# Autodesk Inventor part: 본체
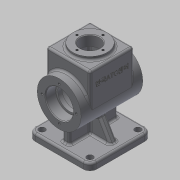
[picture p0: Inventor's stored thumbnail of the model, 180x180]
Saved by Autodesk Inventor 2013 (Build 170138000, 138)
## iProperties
Created: 2019-01
Part Number: 본체
Material: 일반
Document SubType Name: Modeling
Designer: mduedu
Density: 1 g/cm^3
Author: mduedu
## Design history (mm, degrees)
sketch "스케치1"
  geometry: C1 r 32 at (0, 0); 1 further point
  constraints: 1 centre point, 1 coincident
  dimensions: "d0" = 64 diameter of C1
extrude "돌출1" new body sketch "스케치1" stored distance "d1" = 90; taper "d2" = 0 deg
sketch "스케치2"
  geometry: L1 (0, 32)-(50, 32); L2 (50, 32)-(50, -32); L3 (50, -32)-(0, -32); L4 (0, -32)-(0, 32); C1 r 32 at (0, 0) reference; 2 further points
  constraints: 8 end point, 2 parallel, 1 coincident, 1 horizontal, 1 midpoint, 1 perpendicular, 1 tangent
  dimensions: "d5" = 50 distance between parallel lines of L4 L2
extrude "돌출2" join sketch "스케치2" stored distance "d7" = 64; taper "d8" = 0 deg
sketch "스케치3"
  geometry: C1 r 25 at (32, 32); 1 further point
  constraints: 1 centre point, 1 coincident
  dimensions: "d9" = 50 diameter of C1
extrude "돌출3" join sketch "스케치3" distance "d10" = 5; taper "d11" = 0 deg
sketch "스케치4"
  geometry: L1 (40, 25)-(0, 25); L2 (0, 25)-(0, -25); L3 (0, -25)-(40, -25); L4 (40, -25)-(40, 25); L5 (55, -25)-(55, 25) reference; A1 r 25 centre (0, 0) between (0, 25) and (0, -25); A2 r 25 centre (0, 0) between (0, -25) and (0, 25); 2 further points
  constraints: 8 end point, 4 point on circle, 2 centre point, 2 coincident, 2 parallel, 1 horizontal, 1 midpoint, 1 perpendicular, 1 tangent
  dimensions: "d12" = 50 diameter of A1; "d13" = 15 distance between parallel lines of L4 L5
extrude "돌출4" cut sketch "스케치4" stored distance "d14" = 48; taper "d15" = 0 deg
sketch "스케치5"
  geometry: C1 r 20 at (0, 0); 1 further point
  constraints: 1 centre point, 1 coincident
  dimensions: "d16" = 40 diameter of C1
extrude "돌출5" cut sketch "스케치5" distance "d17" = 15; taper "d18" = 0 deg
sketch "스케치6"
  geometry: C1 r 17 at (0, 0); 1 further point
  constraints: 1 centre point, 1 coincident
  dimensions: "d19" = 34 diameter of C1
extrude "돌출6" cut sketch "스케치6" stored distance "d20" = 15; taper "d21" = 0 deg
fillet "모깎기1" dims "d22" = 0.3
fillet "모깎기2" dims "d23" = 3
fillet "모깎기3" dims "d24" = 3
fillet "모깎기4" dims "d25" = 3
fillet "모깎기5" dims "d26" = 3
fillet "모깎기6" dims "d27" = 3
sketch "스케치7"
  geometry: C1 r 14 at (0, 0); 1 further point
  constraints: 1 centre point, 1 coincident
  dimensions: "d28" = 28 diameter of C1
extrude "돌출7" cut sketch "스케치7" stored distance "d29" = 15; taper "d30" = 0 deg
chamfer "모따기1" distance "d31" = 1; stored, may be unused: second distance "d32" = 2, angle "d33" = 45 deg
chamfer "모따기2" distance "d34" = 1; stored, may be unused: second distance "d35" = 2, angle "d36" = 45 deg
node "작업 평면1"
sketch "스케치8"
  geometry: L1 (45, -45)-(-45, -45); L2 (-45, -45)-(-45, 45); L3 (-45, 45)-(45, 45); L4 (45, 45)-(45, -45); 3 further points
  constraints: 8 end point, 2 midpoint, 2 parallel, 1 horizontal, 1 horizontal alignment, 1 perpendicular, 1 vertical alignment
  dimensions: "d39" = 90 distance of L1.start L1.end; "d40" = 90 distance of L1.end L2.end
extrude "돌출8" join sketch "스케치8" distance "d41" = 10; taper "d42" = 0 deg
sketch "스케치9"
  geometry: L1 (-35, 5)-(35, 5); L2 (35, 5)-(35, -5); L3 (35, -5)-(-35, -5); L4 (-35, -5)-(-35, 5); 3 further points
  constraints: 8 end point, 2 midpoint, 2 parallel, 1 horizontal, 1 horizontal alignment, 1 perpendicular, 1 vertical alignment
  dimensions: "d52" = 10 distance of L1.end L2.end; "d54" = 70 distance of L1.start L1.end
extrude "돌출9" join sketch "스케치9" stored distance "d50" = 10; taper "d51" = 0 deg
sketch "스케치10"
  geometry: L1 (0, -25)-(37, -25) reference; L2 (40, -22)-(40, -14) reference; L3 (40, -14)-(54, -14) reference; L4 (54, -14)-(55, -15) reference; L5 (55, -15)-(55, -25) reference; L6 (55, -25)-(53, -25) reference; L7 (50, -28)-(50, -29) reference; L8 (47, -32)-(0, -32) reference; L9 (-31.607, -5)-(-55, -5) reference; L10 (-55, -5)-(-55, -45) reference; L11 (-55, -45)-(-65, -45) reference; L12 (-65, -45)-(-65, 45) reference; L13 (-65, 45)-(-55, 45) reference; L14 (-55, 45)-(-55, 5) reference; L15 (-55, 5)-(-31.607, 5) reference; L16 (0, 32)-(47, 32) reference; L17 (50, 29)-(50, 28) reference; L18 (53, 25)-(55, 25) reference; L19 (55, 25)-(55, 15) reference; L20 (55, 15)-(54, 14) reference; L21 (54, 14)-(40, 14) reference; L22 (40, 14)-(40, 22) reference; L23 (37, 25)-(0, 25) reference; L24 (-55, 35)-(-26.2, 18.372); A1 r 25 centre (0, 0) between (0, 25) and (0, -25) reference; A2 r 3 centre (37, -22) between (37, -25) and (40, -22) reference; A3 r 3 centre (53, -28) between (53, -25) and (50, -28) reference; A4 r 3 centre (47, -29) between (47, -32) and (50, -29) reference; A5 r 32 centre (0, 0) between (-31.607, -5) and (0, -32) reference; A6 r 32 centre (0, 0) between (0, 32) and (-31.607, 5) reference; A7 r 3 centre (47, 29) between (50, 29) and (47, 32) reference; A8 r 3 centre (53, 28) between (50, 28) and (53, 25) reference; A9 r 3 centre (37, 22) between (40, 22) and (37, 25) reference; 1 further point
  constraints: 2 end point, 1 point on circle, 1 point on line
  dimensions: "d55" = 35 vertical distance of L24.start point (0, 0); "d56" = 120 deg angle of L24 L14
feature "리브1" sketch "스케치10" dims "d57" = 1, "d58" = 10, "d59" = 0, "d60" = 0, "d61" = 1, "d62" = 1
fillet "모깎기7" dims "d63" = 3
fillet "모깎기8" dims "d64" = 3
fillet "모깎기9" dims "d65" = 10
sketch "스케치11"
  geometry: L1 (-45, 35)-(-45, -35) reference; L2 (-35, -45)-(35, -45) reference; L3 (45, -35)-(45, 35) reference; L4 (35, 45)-(-35, 45) reference; L5 (8, -29.804)-(8, -8) reference; L6 (-2, -36.732)-(2, -36.732) reference; L7 (-8, -8)-(-8, -29.804) reference; L8 (-32, -8)-(-8, -8) reference; L9 (-38, 2)-(-38, -2) reference; L10 (-8, 8)-(-32, 8) reference; L11 (-8, 29.804)-(-8, 8) reference; L12 (2, 36.732)-(-2, 36.732) reference; L13 (8, 8)-(8, 29.804) reference; L14 (32, 8)-(8, 8) reference; L15 (38, -2)-(38, 2) reference; L16 (8, -8)-(32, -8) reference; A1 r 10 centre (-35, 35) between (-35, 45) and (-45, 35) reference; A2 r 10 centre (-35, -35) between (-45, -35) and (-35, -45) reference; A3 r 10 centre (35, -35) between (35, -45) and (45, -35) reference; A4 r 10 centre (35, 35) between (45, 35) and (35, 45) reference; A5 r 6 centre (-32, -2) between (-38, -2) and (-32, -8) reference; A6 r 6 centre (-32, 2) between (-32, 8) and (-38, 2) reference; A7 r 6 centre (32, 2) between (38, 2) and (32, 8) reference; A8 r 6 centre (32, -2) between (32, -8) and (38, -2) reference; 9 further points; 4 other entities
  constraints: 4 coincident, 4 other
hole "구멍1" sketch "스케치11" at (-35, 35), (35, 35), (35, -35), (-35, -35) diameter "d66" = 9; stored, may be unused: countersink angle "d70" = 90 deg, drill point angle "d72" = 118 deg; dims "d67" = 6, "d68" = 4, "d69" = 2, "d71" = 8
fillet "모깎기10" dims "d73" = 3
sketch "스케치12"
  geometry: L1 (-3, 47)-(-3, 19.596) reference; 2 further points
  constraints: 1 other
  dimensions: "d74" = 32 distance from line of point (29, 30) L1; "d75" = 30 distance of point (29, 30) point (29, 0)
feature "엠보싱1" sketch "스케치12" dims "d76" = 0.5, "d77" = 0
sketch "스케치13"
  geometry: 4 further points
  constraints: 4 other
hole "구멍2" sketch "스케치13" at (-25, 0), (0, -25), (25, 0), (0, 25) diameter "d78" = 3.242; stored, may be unused: countersink angle "d82" = 90 deg, drill point angle "d84" = 120 deg; dims "d79" = 7, "d80" = 4, "d81" = 2, "d83" = 9
sketch "스케치14"
  geometry: 4 further points
  constraints: 4 other
hole "구멍3" sketch "스케치14" at (-25, 0), (0, -25), (25, 0), (0, 25) diameter "d85" = 3.242; stored, may be unused: countersink angle "d89" = 90 deg, drill point angle "d91" = 120 deg; dims "d86" = 7, "d87" = 4, "d88" = 2, "d90" = 9
sketch "스케치15"
  geometry: 4 further points
  constraints: 4 other
hole "구멍4" sketch "스케치15" at (0, -19), (19, 0), (0, 19), (-19, 0) diameter "d92" = 3.242; stored, may be unused: countersink angle "d96" = 90 deg, drill point angle "d98" = 120 deg; dims "d93" = 8, "d94" = 4, "d95" = 2, "d97" = 10
node "솔리드1"
mirror "대칭1"
mirror "대칭2"
node "투영된 루프1"
node "절단 모서리 투영1"
node "절단 모서리 투영2"
other parameters: "d37" = -65
